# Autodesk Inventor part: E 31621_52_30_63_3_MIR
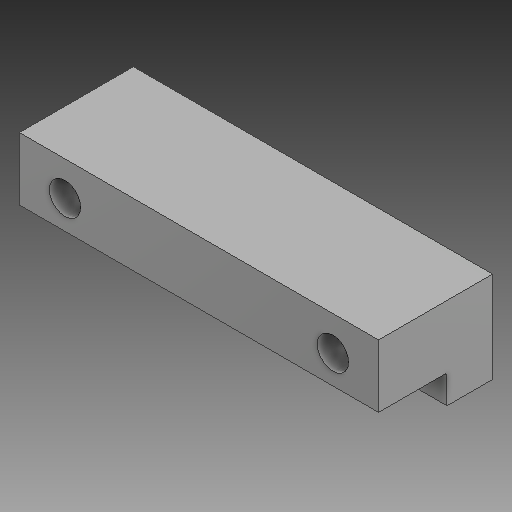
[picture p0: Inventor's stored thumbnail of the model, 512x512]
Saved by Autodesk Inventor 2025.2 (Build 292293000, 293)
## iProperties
Created: 2025-03
Part Number: E 31621_52_30_63_3_MIR
Material: Všeobecné
Document SubType Name: Modeling
Designer: Patrik
Mass: 14.8663 g
Surface Area: 57.9217 cm^2
Volume: 14.8663 cm^3
Density: 1 g/cm^3
Appearance: Výchozí
Author: Patrik
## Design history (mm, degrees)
derived "E 31621_52_30_63_3.ipt"
feature "Těleso1::E 31621_52_30_63_3.ipt" dims "d0" = 10
tag "Prvek štítků1"
node "Těleso1"
